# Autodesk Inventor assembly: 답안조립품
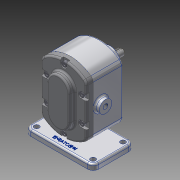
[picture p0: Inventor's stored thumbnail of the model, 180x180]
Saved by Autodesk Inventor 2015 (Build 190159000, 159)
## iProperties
Created: 2019-03
Part Number: 답안조립품
Document SubType Name: Assembly
Designer: Administrator
Author: Administrator
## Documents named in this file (10)
- C:\Users\Administrator.SC-201902081457\Desktop\490307V1048\답안조립품.iam
- C:\Users\Administrator.SC-201902081457\Desktop\490307V1048\본체.ipt
- C:\Users\Administrator.SC-201902081457\Desktop\490307V1048\커버.ipt
- C:\Users\Administrator.SC-201902081457\Desktop\490307V1048\볼트 M5.ipt
- C:\Users\Administrator.SC-201902081457\Desktop\490307V1048\오일 실 16 28 7.ipt
- C:\Users\Administrator.SC-201902081457\Desktop\490307V1048\베어링부시.ipt
- C:\Users\Administrator.SC-201902081457\Desktop\490307V1048\메인축.ipt
- C:\Users\Administrator.SC-201902081457\Desktop\490307V1048\키 6 x 6 x 18.ipt
- C:\Users\Administrator.SC-201902081457\Desktop\490307V1048\스퍼기어.ipt
- C:\Users\Administrator.SC-201902081457\Desktop\490307V1048\서브축.ipt
